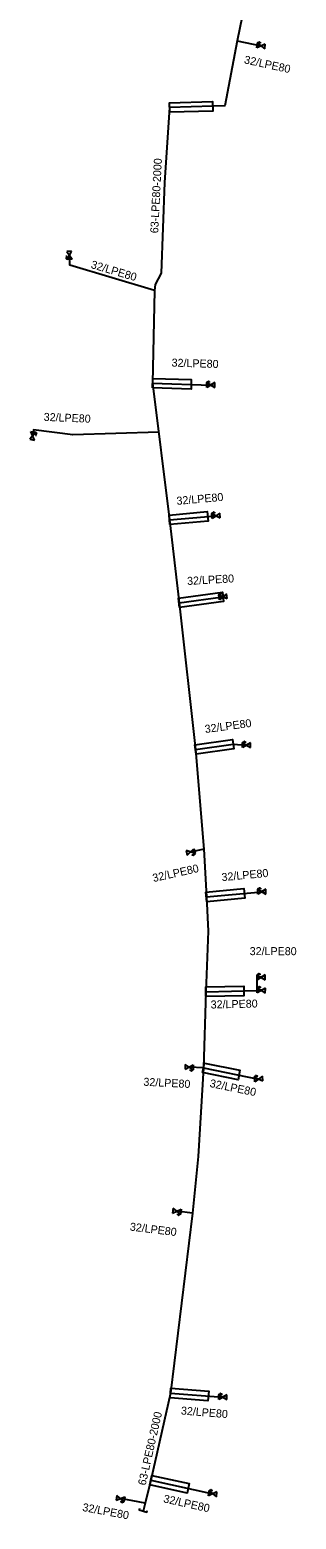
# Model space of a CAD drawing. Extents: x -741323 to -735641, y -1146295 to -1143223.
# Drawn here: x -736551.4 to -736518.1, y -1143780.8 to -1143594.7 of the extents above; entities that cross this region are included whole.
import ezdxf

# ---------------------------------------------------------------- set-up
doc = ezdxf.new("R2010")
doc.units = 0
for name, color, linetype in [('Vrstva 1', 7, 'Continuous'), ('Vrstva 21', 7, 'Continuous'), ('Vrstva 22', 7, 'Continuous'), ('Vrstva 29', 7, 'Continuous'), ('Vrstva 31', 7, 'Continuous'), ('Vrstva 32', 7, 'Continuous')]:
    doc.layers.add(name, color=color, linetype=linetype)

# ---------------------------------------------------------------- blocks, each defined once
blk = doc.blocks.new('DEC063-SN')
at = {"layer": 'Vrstva 1'}
for p, q in [((-0.5, -0.3), (0.5, 0.3)), ((0.5, -0.3), (-0.5, 0.3)), ((-0.5, 0.3), (-0.5, -0.3)), ((0.5, 0.3), (0.5, -0.3)), ((0.126, -0.318), (0.126, -0.458)), ((0.126, -0.384), (0.206, -0.384)), ((0.206, -0.458), (0.206, -0.318)), ((0.366, -0.458), (0.366, -0.318))]:
    blk.add_line(p, q, dxfattribs=at)
for points in [[(0.246, -0.318), (0.246, -0.418), (0.252, -0.438), (0.264, -0.451), (0.281, -0.458), (0.292, -0.458), (0.309, -0.451), (0.321, -0.438), (0.326, -0.418), (0.326, -0.318)], [(0.366, -0.318), (0.418, -0.318), (0.435, -0.325), (0.441, -0.331), (0.446, -0.344), (0.446, -0.364), (0.441, -0.378), (0.435, -0.384), (0.418, -0.391), (0.366, -0.391)]]:
    blk.add_lwpolyline(points, dxfattribs=at)
blk = doc.blocks.new('DEC130')
at = {"layer": 'Vrstva 1'}
blk.add_lwpolyline([(0.2, 0.5), (0, 0.5), (0, -0.5), (0.2, -0.5)], dxfattribs=at)

msp = doc.modelspace()

# ---------------------------------------------------------------- linework, layer by layer
at = {"layer": 'Vrstva 21'}
msp.add_lwpolyline([(-736524.24, -1143589.94), (-736525.49, -1143596.05), (-736527.04, -1143604.19), (-736528.54, -1143604.23), (-736533.92, -1143604.39), (-736534.58, -1143613.76), (-736534.98, -1143625.11), (-736535.74, -1143626.5), (-736535.83, -1143627.24), (-736536.06, -1143638.84), (-736533.93, -1143655.91), (-736532.75, -1143666.28), (-736530.7, -1143684.62), (-736529.64, -1143697.06), (-736529.33, -1143703.03), (-736529.1, -1143707.33), (-736529.4, -1143714.88), (-736529.68, -1143724.39), (-736530.36, -1143735.48), (-736531.05, -1143742.54), (-736533.81, -1143765.03), (-736536.27, -1143775.91), (-736536.99, -1143778.77), (-736537.25, -1143779.77)], dxfattribs=at)
at = {"layer": 'Vrstva 29'}
for points in [[(-736533.9, -1143604.99), (-736533.94, -1143603.79), (-736528.56, -1143603.63), (-736528.52, -1143604.83)], [(-736536.08, -1143639.44), (-736536.04, -1143638.24), (-736531.21, -1143638.39), (-736531.24, -1143639.59)], [(-736533.88, -1143656.51), (-736533.98, -1143655.31), (-736529.22, -1143654.89), (-736529.12, -1143656.09)], [(-736532.67, -1143666.87), (-736532.83, -1143665.69), (-736527.33, -1143664.94), (-736527.17, -1143666.12)], [(-736530.61, -1143685.21), (-736530.79, -1143684.03), (-736526.06, -1143683.35), (-736525.88, -1143684.53)], [(-736529.27, -1143703.63), (-736529.39, -1143702.43), (-736524.63, -1143701.99), (-736524.52, -1143703.18)], [(-736529.39, -1143715.48), (-736529.41, -1143714.28), (-736524.65, -1143714.18), (-736524.63, -1143715.38)], [(-736529.8, -1143724.98), (-736529.56, -1143723.8), (-736525.13, -1143724.7), (-736525.37, -1143725.88)], [(-736533.86, -1143765.63), (-736533.76, -1143764.43), (-736529.04, -1143764.81), (-736529.13, -1143766)], [(-736536.4, -1143776.5), (-736536.14, -1143775.32), (-736531.49, -1143776.35), (-736531.75, -1143777.52)]]:
    msp.add_lwpolyline(points, close=True, dxfattribs=at)
at = {"layer": 'Vrstva 31'}
for points in [[(-736525.49, -1143596.05), (-736522.49, -1143596.7)], [(-736535.83, -1143627.24), (-736546.42, -1143624.11), (-736546.45, -1143622.86)], [(-736536.06, -1143638.84), (-736528.79, -1143639.07)], [(-736535.29, -1143644.98), (-736546.02, -1143645.29), (-736550.93, -1143644.67), (-736551.05, -1143645.4)], [(-736533.93, -1143655.91), (-736528.12, -1143655.4)], [(-736532.75, -1143666.28), (-736527.25, -1143665.53)], [(-736530.7, -1143684.62), (-736525.97, -1143683.94), (-736524.31, -1143684.08)], [(-736529.64, -1143697.06), (-736531.3, -1143697.43)], [(-736529.33, -1143703.03), (-736522.41, -1143702.38)], [(-736522.96, -1143714.74), (-736522.99, -1143713.11), (-736522.49, -1143713.09)], [(-736529.4, -1143714.88), (-736522.97, -1143714.74)], [(-736522.97, -1143714.74), (-736522.96, -1143714.74), (-736522.46, -1143714.72)], [(-736529.68, -1143724.39), (-736531.48, -1143724.3)], [(-736529.68, -1143724.39), (-736522.79, -1143725.79)], [(-736531.05, -1143742.54), (-736533.02, -1143742.3)], [(-736533.81, -1143765.03), (-736527.28, -1143765.55)], [(-736536.27, -1143775.91), (-736528.54, -1143777.62)], [(-736536.99, -1143778.77), (-736540.07, -1143778.2)]]:
    msp.add_lwpolyline(points, dxfattribs=at)

# ---------------------------------------------------------------- block references
at = {"layer": 'Vrstva 22', "rotation": 74.12961389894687}
msp.add_blockref('DEC130', (-736537.25, -1143779.77), dxfattribs=at)
at = {"layer": 'Vrstva 32'}
for p, rotation in [((-736522.49, -1143596.7), 172.7155583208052), ((-736546.45, -1143622.86), -85.39713053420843), ((-736528.79, -1143639.07), -179.9011471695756), ((-736551.05, -1143645.4), 81.30089720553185), ((-736528.12, -1143655.4), -176.3571056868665), ((-736527.25, -1143665.53), -171.76902505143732), ((-736524.31, -1143684.08), 179.85729725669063), ((-736531.3, -1143697.43), 12.56534725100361), ((-736522.41, -1143702.38), 179.8056138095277), ((-736522.49, -1143713.09), -179.8847165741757), ((-736522.46, -1143714.72), 177.50269995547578), ((-736531.48, -1143724.3), -2.8624056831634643), ((-736522.79, -1143725.79), -173.5365805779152), ((-736533.02, -1143742.3), -6.945966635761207), ((-736527.28, -1143765.55), 179.80615271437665), ((-736528.54, -1143777.62), 172.78859177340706), ((-736540.07, -1143778.2), -10.484813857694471)]:
    msp.add_blockref('DEC063-SN', p, dxfattribs=dict(at, rotation=rotation))

# ---------------------------------------------------------------- texts
at = {"layer": 'Vrstva 21'}
for rotation, p in [(87.099, (-736535.36, -1143620.12)), (77.259, (-736536.93, -1143776.63))]:
    msp.add_text('63-LPE80-2000', height=1, rotation=rotation, dxfattribs=at).set_placement(p)
at = {"layer": 'Vrstva 31'}
for rotation, p in [(347.775, (-736524.67, -1143598.86)), (343.534, (-736543.85, -1143624.43)), (358.188, (-736533.69, -1143636.76)), (357.601, (-736549.69, -1143643.54)), (5.017, (-736533.02, -1143654.05)), (3.295, (-736531.71, -1143664.06)), (7.669, (-736529.46, -1143682.56)), (12.565, (-736535.94, -1143701.18)), (5.366, (-736527.38, -1143701.07)), (359.972, (-736523.91, -1143710.31)), (1.245, (-736528.78, -1143716.98)), (357.138, (-736537.22, -1143726.62)), (348.514, (-736528.97, -1143726.77)), (353.054, (-736538.94, -1143744.71)), (355.447, (-736532.54, -1143767.7)), (349.515, (-736544.89, -1143779.75)), (347.526, (-736534.77, -1143778.67))]:
    msp.add_text('32/LPE80', height=1, rotation=rotation, dxfattribs=at).set_placement(p)

doc.saveas('drawing.dxf')
